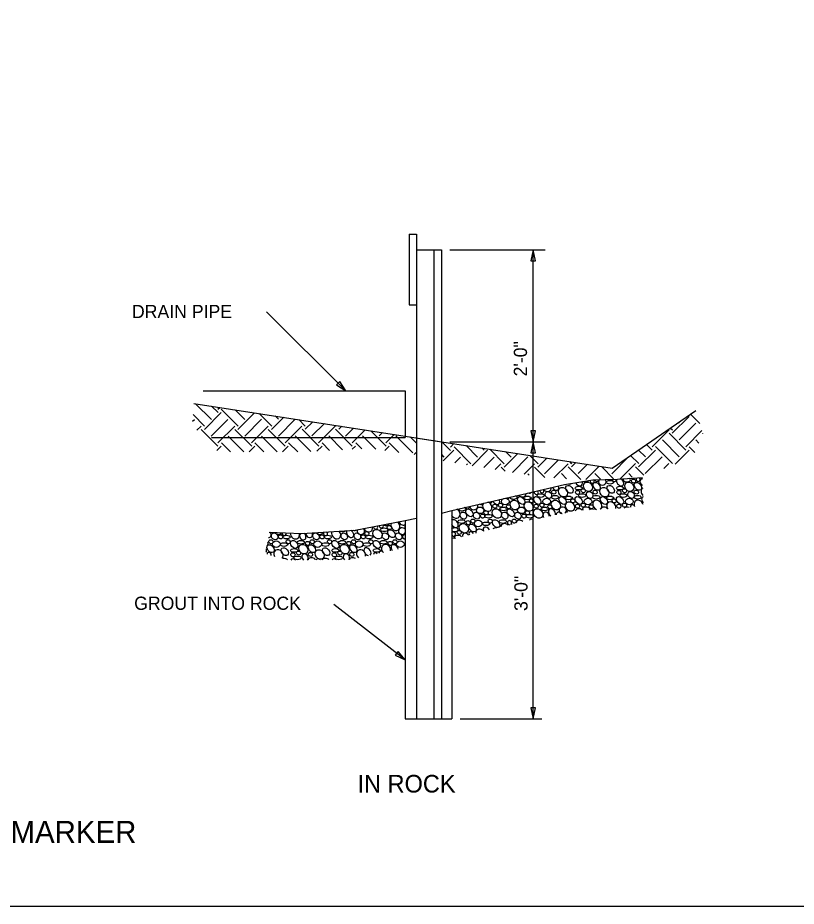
# Model space of a CAD drawing. Extents: x -439.1 to -407.9, y -458.1 to -436.2.
# Drawn here: x -427.15 to -418.31, y -458.05 to -447.96 of the extents above; entities that cross this region are included whole.
import ezdxf

# ---------------------------------------------------------------- set-up
doc = ezdxf.new("R2010")
doc.units = 0
for name, color, linetype in [('Bridge-Named Boundary', 7, 'Continuous'), ('Level 4', 7, 'Continuous'), ('Level 45', 7, 'Continuous')]:
    doc.layers.add(name, color=color, linetype=linetype)

msp = doc.modelspace()

# ---------------------------------------------------------------- linework, layer by layer
at = {"layer": 'Bridge-Named Boundary'}
msp.add_lwpolyline([(-439.109, -458.051), (-407.859, -458.051), (-407.859, -437.676), (-439.109, -437.676)], close=True, dxfattribs=at)
at = {"layer": 'Level 4'}
for p, q in [((-422.705, -450.416), (-422.705, -451.218)), ((-422.705, -450.416), (-422.622, -450.416)), ((-422.622, -450.416), (-422.622, -455.923)), ((-422.622, -450.593), (-422.338, -450.593)), ((-422.422, -450.593), (-422.422, -455.923)), ((-422.338, -450.593), (-422.338, -455.923)), ((-422.24, -450.593), (-421.159, -450.593)), ((-421.296, -452.774), (-421.296, -450.593)), ((-422.705, -451.218), (-422.622, -451.218)), ((-423.423, -452.198), (-424.324, -451.297)), ((-425.044, -452.198), (-422.748, -452.198)), ((-422.748, -452.198), (-422.748, -452.726)), ((-425.149, -452.339), (-425.149, -452.339)), ((-425.149, -452.339), (-420.397, -453.075)), ((-425.13, -452.342), (-424.951, -452.52)), ((-425.03, -452.635), (-424.839, -452.444)), ((-424.948, -452.37), (-424.874, -452.444)), ((-424.877, -452.406), (-424.855, -452.384)), ((-424.839, -452.406), (-424.648, -452.597)), ((-424.68, -452.411), (-424.571, -452.52)), ((-424.649, -452.634), (-424.46, -452.445)), ((-424.5, -452.439), (-424.495, -452.444)), ((-420.397, -453.075), (-419.446, -452.421)), ((-425.164, -452.54), (-425.144, -452.52)), ((-425.158, -452.466), (-425.027, -452.597)), ((-424.953, -452.712), (-424.762, -452.52)), ((-424.572, -452.71), (-424.381, -452.519)), ((-424.406, -452.454), (-424.264, -452.596)), ((-424.266, -452.634), (-424.129, -452.497)), ((-424.225, -452.482), (-424.188, -452.519)), ((-424.19, -452.711), (-423.999, -452.519)), ((-423.957, -452.523), (-423.884, -452.596)), ((-423.885, -452.633), (-423.8, -452.548)), ((-419.715, -452.678), (-419.524, -452.487)), ((-419.507, -452.463), (-419.403, -452.566)), ((-425.115, -452.644), (-425.068, -452.597)), ((-425.068, -452.635), (-424.877, -452.826)), ((-424.877, -452.788), (-424.686, -452.597)), ((-424.684, -452.634), (-424.493, -452.825)), ((-424.495, -452.787), (-424.305, -452.596)), ((-424.305, -452.634), (-424.114, -452.825)), ((-424.114, -452.787), (-423.922, -452.596)), ((-423.921, -452.633), (-423.73, -452.824)), ((-423.809, -452.709), (-423.667, -452.568)), ((-423.732, -452.786), (-423.541, -452.595)), ((-423.542, -452.633), (-423.35, -452.824)), ((-423.503, -452.633), (-423.469, -452.599)), ((-423.501, -452.594), (-423.5, -452.595)), ((-423.427, -452.71), (-423.336, -452.619)), ((-423.35, -452.786), (-423.204, -452.64)), ((-423.14, -452.65), (-422.966, -452.823)), ((-419.943, -452.832), (-419.752, -452.641)), ((-419.735, -452.62), (-419.714, -452.641)), ((-419.644, -452.557), (-419.637, -452.564)), ((-419.638, -452.754), (-419.448, -452.563)), ((-419.562, -452.831), (-419.379, -452.648)), ((-424.949, -452.726), (-422.748, -452.726)), ((-424.761, -452.71), (-424.582, -452.89)), ((-424.381, -452.71), (-424.202, -452.89)), ((-423.998, -452.709), (-423.822, -452.885)), ((-423.618, -452.709), (-423.461, -452.866)), ((-423.234, -452.708), (-423.084, -452.859)), ((-423.045, -452.708), (-423.007, -452.67)), ((-422.969, -452.785), (-422.875, -452.691)), ((-422.854, -452.708), (-422.663, -452.9)), ((-422.691, -452.719), (-422.622, -452.789)), ((-422.607, -452.732), (-422.338, -452.774)), ((-419.751, -452.678), (-419.56, -452.869)), ((-419.371, -452.678), (-419.371, -452.679)), ((-424.888, -452.873), (-424.84, -452.825)), ((-424.837, -452.787), (-424.734, -452.89)), ((-424.522, -452.89), (-424.457, -452.825)), ((-424.458, -452.787), (-424.355, -452.89)), ((-424.142, -452.89), (-424.077, -452.824)), ((-424.074, -452.786), (-423.97, -452.89)), ((-423.751, -452.881), (-423.694, -452.824)), ((-423.694, -452.786), (-423.607, -452.874)), ((-423.35, -452.86), (-423.313, -452.823)), ((-423.311, -452.785), (-423.241, -452.854)), ((-422.981, -452.873), (-422.931, -452.823)), ((-422.931, -452.785), (-422.821, -452.895)), ((-422.338, -452.774), (-422.338, -452.774)), ((-422.332, -452.775), (-422.233, -452.873)), ((-422.24, -452.774), (-421.195, -452.774)), ((-422.24, -452.774), (-421.159, -452.774)), ((-422.233, -452.835), (-422.195, -452.796)), ((-422.194, -452.833), (-422.002, -453.025)), ((-422.057, -452.818), (-421.926, -452.948)), ((-421.876, -452.846), (-421.85, -452.872)), ((-421.296, -455.923), (-421.296, -452.774)), ((-420.007, -452.807), (-419.943, -452.87)), ((-419.904, -452.83), (-419.712, -453.022)), ((-419.827, -452.754), (-419.636, -452.945)), ((-419.524, -452.831), (-419.458, -452.897)), ((-419.448, -452.754), (-419.412, -452.79)), ((-422.647, -452.919), (-422.621, -452.893)), ((-422.338, -452.921), (-422.31, -452.949)), ((-422.317, -452.993), (-422.196, -452.872)), ((-422.186, -453.015), (-422.12, -452.948)), ((-421.989, -453.047), (-421.814, -452.872)), ((-421.857, -453.068), (-421.737, -452.948)), ((-421.789, -452.859), (-421.623, -453.025)), ((-421.624, -453.062), (-421.47, -452.908)), ((-421.608, -452.887), (-421.546, -452.948)), ((-421.531, -453.122), (-421.356, -452.947)), ((-421.333, -452.93), (-421.239, -453.024)), ((-420.402, -453.138), (-420.211, -452.947)), ((-420.188, -452.931), (-420.096, -453.023)), ((-420.097, -453.06), (-419.906, -452.869)), ((-420.097, -452.869), (-420.02, -452.946)), ((-420.021, -453.136), (-419.83, -452.945)), ((-419.683, -453.028), (-419.524, -452.869)), ((-422.054, -453.036), (-422.043, -453.025)), ((-421.726, -453.09), (-421.661, -453.025)), ((-421.399, -453.143), (-421.28, -453.024)), ((-421.242, -453.062), (-421.139, -452.96)), ((-421.165, -453.139), (-421.007, -452.98)), ((-421.06, -453.186), (-420.898, -453.024)), ((-420.884, -452.999), (-420.86, -453.024)), ((-420.861, -453.061), (-420.81, -453.011)), ((-420.784, -453.137), (-420.678, -453.031)), ((-420.695, -453.202), (-420.545, -453.052)), ((-420.307, -453.195), (-420.134, -453.023)), ((-419.81, -453.079), (-419.753, -453.022)), ((-421.66, -453.062), (-421.613, -453.108)), ((-421.356, -453.138), (-421.342, -453.153)), ((-421.28, -453.062), (-421.162, -453.18)), ((-420.973, -453.137), (-420.916, -453.194)), ((-420.896, -453.061), (-420.754, -453.203)), ((-420.593, -453.137), (-420.531, -453.199)), ((-420.517, -453.061), (-420.382, -453.196)), ((-420.21, -453.136), (-420.171, -453.175)), ((-420.133, -453.06), (-420.037, -453.155)), ((-420.938, -453.261), (-420.777, -453.234)), ((-420.777, -453.234), (-420.617, -453.206)), ((-420.617, -453.206), (-420.336, -453.201)), ((-420.336, -453.201), (-420.054, -453.182)), ((-421.424, -453.372), (-420.938, -453.261)), ((-422.221, -453.554), (-421.424, -453.372)), ((-422.338, -453.587), (-422.221, -453.554)), ((-422.221, -453.554), (-422.221, -455.923)), ((-422.748, -453.67), (-422.622, -453.643)), ((-423.316, -453.778), (-422.748, -453.67)), ((-422.748, -453.67), (-422.748, -455.923)), ((-424.294, -453.803), (-423.923, -453.818)), ((-424.294, -453.803), (-423.923, -453.818)), ((-423.923, -453.818), (-423.316, -453.778)), ((-422.748, -455.253), (-423.559, -454.624)), ((-422.748, -455.923), (-422.221, -455.923)), ((-422.123, -455.923), (-421.195, -455.923))]:
    msp.add_line(p, q, dxfattribs=at)
for points in [[(-421.27, -450.718), (-421.296, -450.593), (-421.322, -450.718)], [(-423.529, -452.129), (-423.423, -452.198), (-423.493, -452.092)], [(-423.529, -452.129), (-423.423, -452.198), (-423.493, -452.092)], [(-421.322, -452.65), (-421.296, -452.774), (-421.27, -452.65)], [(-421.27, -452.899), (-421.296, -452.774), (-421.322, -452.899)], [(-422.862, -455.197), (-422.748, -455.253), (-422.83, -455.157)], [(-422.862, -455.197), (-422.748, -455.253), (-422.83, -455.157)], [(-421.322, -455.798), (-421.296, -455.923), (-421.27, -455.798)]]:
    msp.add_lwpolyline(points, close=True, dxfattribs=at)
for centre, major_axis, ratio, start_param, end_param in [((-420.891, -453.234), (-0.0413, 0), 0.5, 1.418395, 2.385333), ((-420.778, -453.232), (-0.0323, 0.0389), 0.675732, 1.244251, 4.29537), ((-420.701, -453.208), (-0.0413, 0), 0.5, 0.956726, 2.847001), ((-420.625, -453.221), (0.0192, -0.0155), 0.898968, 3.452229, 7.713162), ((-420.571, -453.203), (0.0192, -0.0155), 0.898968, 4.005449, 6.916047), ((-420.51, -453.23), (-0.0423, 0), 0.885781, 5.551909, 10.196358), ((-420.375, -453.203), (0.0192, -0.0155), 0.898968, 3.854297, 7.0672), ((-420.308, -453.232), (-0.0323, 0.0389), 0.675732, 0.309949, 5.045318), ((-420.231, -453.208), (-0.0413, 0), 0.5, 5.698839, 10.274594), ((-420.102, -453.203), (0.0192, -0.0155), 0.898968, 3.116569, 7.903361), ((-420.04, -453.23), (-0.0423, 0), 0.885781, 5.048485, 7.57515), ((-421.353, -453.315), (-0.0323, 0.0389), 0.675732, 2.212122, 3.408998), ((-421.26, -453.35), (0.0192, -0.0155), 0.898968, 3.386698, 7.941842), ((-421.196, -453.331), (0.0192, -0.0155), 0.898968, 3.638984, 7.689557), ((-421.142, -453.285), (0.0368, -0.0447), 0.82799, 4.730439, 7.047748), ((-421.044, -453.281), (-0.0323, 0.0389), 0.675732, 1.342631, 4.278489), ((-420.017, -453.347), (0.0368, -0.0447), 0.82799, 3.068491, 4.85808), ((-421.784, -453.446), (0.0192, -0.0155), 0.898968, 4.406736, 6.924935), ((-421.717, -453.442), (-0.0323, 0.0389), 0.675732, 1.178547, 4.445026), ((-421.592, -453.379), (-0.0206, 0.0361), 0.832704, 2.156945, 3.631459), ((-421.518, -453.405), (-0.0413, 0), 0.5, 6.153423, 10.411914), ((-421.426, -453.347), (0.0368, -0.0447), 0.82799, 4.77864, 7.000732), ((-420.567, -453.493), (0.0368, -0.0447), 0.82799, 6.1527, 11.587837), ((-420.408, -453.511), (0.0368, -0.0447), 0.82799, 0.549356, 4.62481), ((-420.097, -453.493), (0.0368, -0.0447), 0.82799, 1.068786, 4.398644), ((-420.021, -453.442), (-0.0323, 0.0389), 0.675732, 6.071424, 7.925179), ((-422.178, -453.589), (0.0368, -0.0447), 0.82799, 4.524708, 8.358404), ((-422.103, -453.538), (-0.0413, 0), 0.5, 6.182134, 10.383203), ((-422.044, -453.513), (0.0192, -0.0155), 0.898968, 4.114092, 7.217579), ((-421.976, -453.493), (0.0368, -0.0447), 0.82799, 4.406445, 7.374593), ((-421.9, -453.442), (-0.0323, 0.0389), 0.675732, 2.153922, 3.469651), ((-421.817, -453.511), (0.0368, -0.0447), 0.82799, 3.291491, 8.489547), ((-421.081, -453.582), (-0.0323, 0.0389), 0.675732, 3.652628, 8.21669), ((-420.959, -453.554), (-0.0423, 0), 0.885781, 2.195272, 7.679859), ((-420.891, -453.581), (0.0192, -0.0155), 0.898968, 1.156595, 3.844261), ((-420.769, -453.589), (0.0368, -0.0447), 0.82799, 1.759794, 3.56311), ((-420.694, -453.538), (-0.0413, 0), 0.5, 2.719727, 6.889727), ((-420.611, -453.582), (-0.0323, 0.0389), 0.675732, 5.221598, 6.400264), ((-420.489, -453.554), (-0.0423, 0), 0.885781, 3.597937, 5.931288), ((-420.224, -453.538), (-0.0413, 0), 0.5, 4.179535, 5.783476), ((-420.166, -453.513), (0.0192, -0.0155), 0.898968, 0.952297, 4.062795), ((-422.187, -453.705), (-0.0323, 0.0389), 0.675732, 1.285067, 6.363157), ((-421.314, -453.676), (0.0192, -0.0155), 0.898968, 1.564744, 3.436112), ((-421.148, -453.613), (-0.0206, 0.0361), 0.832704, 4.081718, 7.947931), ((-420.998, -453.613), (-0.0206, 0.0361), 0.832704, 4.827481, 7.202168), ((-423.171, -453.746), (0.0368, -0.0447), 0.82799, 4.359744, 7.357162), ((-423.085, -453.743), (0.0192, -0.0155), 0.898968, 3.66901, 7.592313), ((-423.02, -453.731), (0.0192, -0.0155), 0.898968, 3.687015, 7.574308), ((-422.966, -453.69), (-0.0423, 0), 0.885781, 0.799394, 2.766553), ((-422.861, -453.729), (0.0368, -0.0447), 0.82799, 3.5709, 8.146006), ((-422.783, -453.79), (-0.0423, 0), 0.885781, 3.726139, 8.840232), ((-422.785, -453.678), (-0.0323, 0.0389), 0.675732, 1.198634, 3.35517), ((-422.702, -453.746), (0.0368, -0.0447), 0.82799, 3.448074, 4.412213), ((-422.785, -453.678), (-0.0323, 0.0389), 0.675732, 4.293055, 4.369541), ((-422.187, -453.774), (-0.0413, 0), 0.5, 0.587192, 5.695993), ((-421.823, -453.788), (-0.0323, 0.0389), 0.675732, 4.51687, 7.425647), ((-421.717, -453.774), (-0.0413, 0), 0.5, 4.500152, 5.86325), ((-421.612, -453.758), (0.0368, -0.0447), 0.82799, 1.717671, 3.821861), ((-421.564, -453.694), (0.0192, -0.0155), 0.898968, 6.04838, 11.612288), ((-421.514, -453.754), (-0.0323, 0.0389), 0.675732, 5.904278, 6.038239), ((-421.449, -453.703), (-0.0423, 0), 0.885781, 3.742982, 6.162773), ((-424.314, -453.818), (-0.0323, 0.0389), 0.675732, 2.505798, 4.534231), ((-424.192, -453.79), (-0.0423, 0), 0.885781, 0.443867, 2.605587), ((-424.125, -453.817), (0.0192, -0.0155), 0.898968, 3.532993, 7.26884), ((-424.002, -453.825), (0.0368, -0.0447), 0.82799, 3.893232, 7.399087), ((-423.912, -453.849), (-0.0206, 0.0361), 0.832704, 0.236814, 5.205605), ((-423.844, -453.818), (-0.0323, 0.0389), 0.675732, 1.003129, 4.368626), ((-423.723, -453.79), (-0.0423, 0), 0.885781, 0.497258, 2.793371), ((-423.655, -453.817), (0.0192, -0.0155), 0.898968, 3.172652, 7.846018), ((-423.641, -453.746), (0.0368, -0.0447), 0.82799, 5.497811, 5.99631), ((-423.533, -453.825), (0.0368, -0.0447), 0.82799, 3.547034, 7.947088), ((-423.458, -453.774), (-0.0413, 0), 0.5, 0.830223, 2.57436), ((-423.375, -453.818), (-0.0323, 0.0389), 0.675732, 0.202277, 5.169478), ((-423.331, -453.729), (0.0368, -0.0447), 0.82799, 5.343647, 6.258222), ((-423.253, -453.79), (-0.0423, 0), 0.885781, 5.836947, 10.29537), ((-422.755, -453.855), (0.0192, -0.0155), 0.898968, 1.889609, 5.646303), ((-422.2, -453.823), (0.0192, -0.0155), 0.898968, 4.185463, 9.633634), ((-422.149, -453.859), (-0.0413, 0), 0.5, 3.324149, 7.039254), ((-422.062, -453.852), (-0.0206, 0.0361), 0.832704, 4.696212, 7.415741), ((-422.001, -453.819), (0.0192, -0.0155), 0.898968, 0.598208, 4.49609), ((-421.895, -453.82), (0.0368, -0.0447), 0.82799, 1.527733, 4.011798), ((-424.328, -453.93), (0.0192, -0.0155), 0.898968, 5.769125, 7.740011), ((-422.966, -453.994), (0.0368, -0.0447), 0.82799, 0.576895, 4.893547), ((-422.868, -453.989), (-0.0323, 0.0389), 0.675732, 4.054178, 7.828959), ((-422.716, -453.943), (-0.0413, 0), 0.5, 5.607781, 6.958589), ((-422.187, -453.915), (-0.0323, 0.0389), 0.675732, 5.340218, 6.363157), ((-424.375, -453.994), (0.0368, -0.0447), 0.82799, 0.237888, 1.019076), ((-424.295, -454.054), (0.0192, -0.0155), 0.898968, 0.223915, 3.817924), ((-424.189, -454.055), (0.0368, -0.0447), 0.82799, 0.02976, 4.523204), ((-423.886, -454.088), (-0.0206, 0.0361), 0.832704, 3.420889, 8.270265), ((-423.416, -454.088), (-0.0206, 0.0361), 0.832704, 3.543969, 8.148977), ((-423.25, -454.055), (0.0368, -0.0447), 0.82799, 0.611627, 4.858814), ((-423.177, -454.024), (-0.0323, 0.0389), 0.675732, 3.126474, 8.756663), ((-423.085, -454.059), (0.0192, -0.0155), 0.898968, 1.31203, 3.706365), ((-423.02, -454.039), (0.0192, -0.0155), 0.898968, 1.053821, 3.964574), ((-424.125, -454.122), (-0.0413, 0), 0.5, 3.353413, 5.067176), ((-424.011, -454.151), (-0.0323, 0.0389), 0.675732, 4.995667, 6.559614), ((-423.812, -454.114), (-0.0413, 0), 0.5, 2.991597, 6.462157), ((-423.724, -454.151), (-0.0323, 0.0389), 0.675732, 5.063993, 6.491288), ((-423.655, -454.122), (-0.0413, 0), 0.5, 3.437512, 6.016242), ((-423.542, -454.151), (-0.0323, 0.0389), 0.675732, 5.110482, 6.444799), ((-423.342, -454.114), (-0.0413, 0), 0.5, 3.954468, 6.273325)]:
    msp.add_ellipse(centre, major_axis=major_axis, ratio=ratio, start_param=start_param, end_param=end_param, dxfattribs=at)
for centre, major_axis, ratio in [((-420.672, -453.285), (0.0368, -0.0447), 0.82799), ((-420.574, -453.281), (-0.0323, 0.0389), 0.675732), ((-420.422, -453.234), (-0.0413, 0), 0.5), ((-420.203, -453.285), (0.0368, -0.0447), 0.82799), ((-420.155, -453.221), (0.0192, -0.0155), 0.898968), ((-420.105, -453.281), (-0.0323, 0.0389), 0.675732), ((-421.122, -453.379), (-0.0206, 0.0361), 0.832704), ((-421.062, -453.346), (0.0192, -0.0155), 0.898968), ((-420.956, -453.347), (0.0368, -0.0447), 0.82799), ((-420.883, -453.315), (-0.0323, 0.0389), 0.675732), ((-420.778, -453.301), (-0.0413, 0), 0.5), ((-420.791, -453.35), (0.0192, -0.0155), 0.898968), ((-420.726, -453.331), (0.0192, -0.0155), 0.898968), ((-420.653, -453.379), (-0.0206, 0.0361), 0.832704), ((-420.592, -453.346), (0.0192, -0.0155), 0.898968), ((-420.486, -453.347), (0.0368, -0.0447), 0.82799), ((-420.414, -453.315), (-0.0323, 0.0389), 0.675732), ((-420.308, -453.301), (-0.0413, 0), 0.5), ((-420.321, -453.35), (0.0192, -0.0155), 0.898968), ((-420.257, -453.331), (0.0192, -0.0155), 0.898968), ((-420.183, -453.379), (-0.0206, 0.0361), 0.832704), ((-420.123, -453.346), (0.0192, -0.0155), 0.898968), ((-421.612, -453.454), (-0.0423, 0), 0.885781), ((-421.506, -453.493), (0.0368, -0.0447), 0.82799), ((-421.43, -453.442), (-0.0323, 0.0389), 0.675732), ((-421.347, -453.511), (0.0368, -0.0447), 0.82799), ((-421.361, -453.413), (-0.0413, 0), 0.5), ((-421.314, -453.446), (0.0192, -0.0155), 0.898968), ((-421.248, -453.442), (-0.0323, 0.0389), 0.675732), ((-421.209, -453.386), (-0.0413, 0), 0.5), ((-421.142, -453.454), (-0.0423, 0), 0.885781), ((-421.037, -453.493), (0.0368, -0.0447), 0.82799), ((-421.048, -453.405), (-0.0413, 0), 0.5), ((-420.961, -453.442), (-0.0323, 0.0389), 0.675732), ((-420.877, -453.511), (0.0368, -0.0447), 0.82799), ((-420.891, -453.413), (-0.0413, 0), 0.5), ((-420.844, -453.446), (0.0192, -0.0155), 0.898968), ((-420.778, -453.442), (-0.0323, 0.0389), 0.675732), ((-420.739, -453.386), (-0.0413, 0), 0.5), ((-420.672, -453.454), (-0.0423, 0), 0.885781), ((-420.579, -453.405), (-0.0413, 0), 0.5), ((-420.491, -453.442), (-0.0323, 0.0389), 0.675732), ((-420.422, -453.413), (-0.0413, 0), 0.5), ((-420.375, -453.446), (0.0192, -0.0155), 0.898968), ((-420.308, -453.442), (-0.0323, 0.0389), 0.675732), ((-420.27, -453.386), (-0.0413, 0), 0.5), ((-420.203, -453.454), (-0.0423, 0), 0.885781), ((-420.109, -453.405), (-0.0413, 0), 0.5), ((-422.02, -453.582), (-0.0323, 0.0389), 0.675732), ((-421.898, -453.554), (-0.0423, 0), 0.885781), ((-421.831, -453.581), (0.0192, -0.0155), 0.898968), ((-421.708, -453.589), (0.0368, -0.0447), 0.82799), ((-421.73, -453.507), (0.0192, -0.0155), 0.898968), ((-421.666, -453.495), (0.0192, -0.0155), 0.898968), ((-421.633, -453.538), (-0.0413, 0), 0.5), ((-421.575, -453.513), (0.0192, -0.0155), 0.898968), ((-421.55, -453.582), (-0.0323, 0.0389), 0.675732), ((-421.429, -453.554), (-0.0423, 0), 0.885781), ((-421.361, -453.581), (0.0192, -0.0155), 0.898968), ((-421.239, -453.589), (0.0368, -0.0447), 0.82799), ((-421.26, -453.507), (0.0192, -0.0155), 0.898968), ((-421.196, -453.495), (0.0192, -0.0155), 0.898968), ((-421.164, -453.538), (-0.0413, 0), 0.5), ((-421.105, -453.513), (0.0192, -0.0155), 0.898968), ((-420.791, -453.507), (0.0192, -0.0155), 0.898968), ((-420.726, -453.495), (0.0192, -0.0155), 0.898968), ((-420.635, -453.513), (0.0192, -0.0155), 0.898968), ((-420.321, -453.507), (0.0192, -0.0155), 0.898968), ((-420.257, -453.495), (0.0192, -0.0155), 0.898968), ((-422.088, -453.613), (-0.0206, 0.0361), 0.832704), ((-421.98, -453.676), (0.0192, -0.0155), 0.898968), ((-421.938, -453.613), (-0.0206, 0.0361), 0.832704), ((-421.87, -453.619), (0.0192, -0.0155), 0.898968), ((-421.803, -453.621), (-0.0413, 0), 0.5), ((-421.784, -453.676), (0.0192, -0.0155), 0.898968), ((-421.717, -453.705), (-0.0323, 0.0389), 0.675732), ((-421.618, -453.613), (-0.0206, 0.0361), 0.832704), ((-421.511, -453.676), (0.0192, -0.0155), 0.898968), ((-421.468, -453.613), (-0.0206, 0.0361), 0.832704), ((-421.4, -453.619), (0.0192, -0.0155), 0.898968), ((-421.333, -453.621), (-0.0413, 0), 0.5), ((-422.988, -453.774), (-0.0413, 0), 0.5), ((-422.929, -453.749), (0.0192, -0.0155), 0.898968), ((-422.11, -453.681), (-0.0413, 0), 0.5), ((-422.082, -453.758), (0.0368, -0.0447), 0.82799), ((-422.034, -453.694), (0.0192, -0.0155), 0.898968), ((-421.984, -453.754), (-0.0323, 0.0389), 0.675732), ((-421.919, -453.703), (-0.0423, 0), 0.885781), ((-421.831, -453.707), (-0.0413, 0), 0.5), ((-421.64, -453.681), (-0.0413, 0), 0.5), ((-424.232, -453.849), (-0.0206, 0.0361), 0.832704), ((-424.164, -453.855), (0.0192, -0.0155), 0.898968), ((-424.097, -453.857), (-0.0413, 0), 0.5), ((-423.762, -453.849), (-0.0206, 0.0361), 0.832704), ((-423.694, -453.855), (0.0192, -0.0155), 0.898968), ((-423.627, -453.857), (-0.0413, 0), 0.5), ((-423.442, -453.849), (-0.0206, 0.0361), 0.832704), ((-423.292, -453.849), (-0.0206, 0.0361), 0.832704), ((-423.225, -453.855), (0.0192, -0.0155), 0.898968), ((-423.185, -453.817), (0.0192, -0.0155), 0.898968), ((-423.158, -453.857), (-0.0413, 0), 0.5), ((-423.063, -453.825), (0.0368, -0.0447), 0.82799), ((-422.973, -453.849), (-0.0206, 0.0361), 0.832704), ((-422.905, -453.818), (-0.0323, 0.0389), 0.675732), ((-422.823, -453.849), (-0.0206, 0.0361), 0.832704), ((-422.135, -453.804), (0.0192, -0.0155), 0.898968), ((-424.278, -453.989), (-0.0323, 0.0389), 0.675732), ((-424.274, -453.911), (0.0192, -0.0155), 0.898968), ((-424.213, -453.939), (-0.0423, 0), 0.885781), ((-424.125, -453.943), (-0.0413, 0), 0.5), ((-424.078, -453.911), (0.0192, -0.0155), 0.898968), ((-424.011, -453.941), (-0.0323, 0.0389), 0.675732), ((-423.934, -453.917), (-0.0413, 0), 0.5), ((-423.906, -453.994), (0.0368, -0.0447), 0.82799), ((-423.858, -453.93), (0.0192, -0.0155), 0.898968), ((-423.808, -453.989), (-0.0323, 0.0389), 0.675732), ((-423.805, -453.911), (0.0192, -0.0155), 0.898968), ((-423.743, -453.939), (-0.0423, 0), 0.885781), ((-423.655, -453.943), (-0.0413, 0), 0.5), ((-423.608, -453.911), (0.0192, -0.0155), 0.898968), ((-423.542, -453.941), (-0.0323, 0.0389), 0.675732), ((-423.464, -453.917), (-0.0413, 0), 0.5), ((-423.436, -453.994), (0.0368, -0.0447), 0.82799), ((-423.389, -453.93), (0.0192, -0.0155), 0.898968), ((-423.338, -453.989), (-0.0323, 0.0389), 0.675732), ((-423.335, -453.911), (0.0192, -0.0155), 0.898968), ((-423.273, -453.939), (-0.0423, 0), 0.885781), ((-423.185, -453.943), (-0.0413, 0), 0.5), ((-423.138, -453.911), (0.0192, -0.0155), 0.898968), ((-423.072, -453.941), (-0.0323, 0.0389), 0.675732), ((-422.995, -453.917), (-0.0413, 0), 0.5), ((-422.919, -453.93), (0.0192, -0.0155), 0.898968), ((-422.865, -453.911), (0.0192, -0.0155), 0.898968), ((-422.804, -453.939), (-0.0423, 0), 0.885781), ((-424.117, -454.024), (-0.0323, 0.0389), 0.675732), ((-424.011, -454.009), (-0.0413, 0), 0.5), ((-424.024, -454.059), (0.0192, -0.0155), 0.898968), ((-423.96, -454.039), (0.0192, -0.0155), 0.898968), ((-423.826, -454.054), (0.0192, -0.0155), 0.898968), ((-423.72, -454.055), (0.0368, -0.0447), 0.82799), ((-423.647, -454.024), (-0.0323, 0.0389), 0.675732), ((-423.542, -454.009), (-0.0413, 0), 0.5), ((-423.554, -454.059), (0.0192, -0.0155), 0.898968), ((-423.49, -454.039), (0.0192, -0.0155), 0.898968), ((-423.356, -454.054), (0.0192, -0.0155), 0.898968), ((-423.072, -454.009), (-0.0413, 0), 0.5), ((-423.973, -454.094), (-0.0413, 0), 0.5), ((-423.503, -454.094), (-0.0413, 0), 0.5)]:
    msp.add_ellipse(centre, major_axis=major_axis, ratio=ratio, dxfattribs=at)

# ---------------------------------------------------------------- texts
for s, height, p in [('DRAIN PIPE', 0.15, (-425.853, -451.37)), ('GROUT INTO ROCK', 0.15, (-425.828, -454.684)), ('IN ROCK', 0.2, (-423.291, -456.759)), ('DRAIN MARKER', 0.25, (-428.366, -457.331))]:
    msp.add_text(s, height=height, dxfattribs=at).set_placement(p)
at = {"layer": 'Level 45'}
for s, p in [('2\'-0"', (-421.365, -452.032)), ('3\'-0"', (-421.359, -454.697))]:
    msp.add_text(s, height=0.15, rotation=90, dxfattribs=at).set_placement(p)

doc.saveas('drawing.dxf')
